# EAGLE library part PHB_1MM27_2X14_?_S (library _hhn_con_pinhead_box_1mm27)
Pin Header Box-Type, 1.27mm/0.5"/50mil Pitch, 2x14 Circuits, single gates in schematic Note: see library description for an important note about THT-version
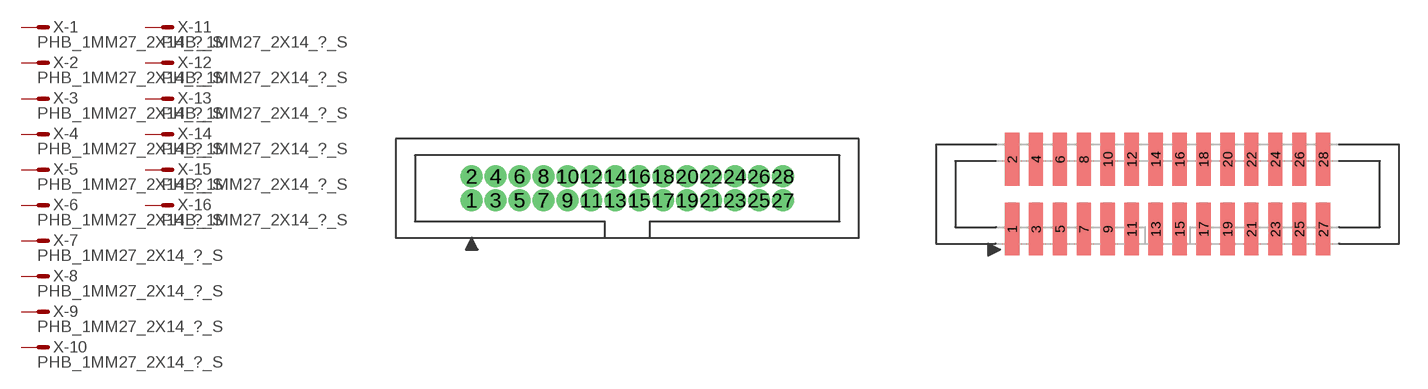
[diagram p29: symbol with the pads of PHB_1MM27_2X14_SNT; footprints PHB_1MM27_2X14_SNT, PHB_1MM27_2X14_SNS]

Designator prefix X; gates -1=M -2=M -3=M -4=M -5=M -6=M -7=M -8=M -9=M -10=M -11=M -12=M -13=M -14=M -15=M -16=M -17=M -18=M -19=M -20=M -21=M -22=M -23=M -24=M -25=M -26=M -27=M -28=M

## PHB_1MM27_2X14_SNT_S  [PHB_1MM27_2X14_SNT]
1  -1:S  pas
2  -2:S  pas
3  -3:S  pas
4  -4:S  pas
5  -5:S  pas
6  -6:S  pas
7  -7:S  pas
8  -8:S  pas
9  -9:S  pas
10  -10:S  pas
11  -11:S  pas
12  -12:S  pas
13  -13:S  pas
14  -14:S  pas
15  -15:S  pas
16  -16:S  pas
17  -17:S  pas
18  -18:S  pas
19  -19:S  pas
20  -20:S  pas
21  -21:S  pas
22  -22:S  pas
23  -23:S  pas
24  -24:S  pas
25  -25:S  pas
26  -26:S  pas
27  -27:S  pas
28  -28:S  pas

## PHB_1MM27_2X14_SNS_S  [PHB_1MM27_2X14_SNS]
Pads as for PHB_1MM27_2X14_SNT

## Footprint PHB_1MM27_2X14_SNT (pad centres in mm)
Pin Header Box-Type, 1.27mm Pitch, 2x14 circuits, Straight, No Locking, THT Important Note: Diameter in this lbr is set to a specific value (NOT 'auto' = 0), this is ignored by actual eagle versions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
drill 0.65 pad 1 round: 1 -8.255,-0.635; 2 -8.255,0.635; 3 -6.985,-0.635; 4 -6.985,0.635; 5 -5.715,-0.635; 6 -5.715,0.635; 7 -4.445,-0.635; 8 -4.445,0.635; 9 -3.175,-0.635; 10 -3.175,0.635; 11 -1.905,-0.635; 12 -1.905,0.635; 13 -0.635,-0.635; 14 -0.635,0.635; 15 0.635,-0.635; 16 0.635,0.635; 17 1.905,-0.635; 18 1.905,0.635; 19 3.175,-0.635; 20 3.175,0.635; 21 4.445,-0.635; 22 4.445,0.635; 23 5.715,-0.635; 24 5.715,0.635; 25 6.985,-0.635; 26 6.985,0.635; 27 8.255,-0.635; 28 8.255,0.635

## Footprint PHB_1MM27_2X14_SNS (pad centres in mm)
Pin Header Box-Type, 1.27mm Pitch, 2x14 circuits, Straight, No Locking, SMT
smd 0.76 x 2.8: 1 -8.255,-1.85; 2 -8.255,1.85; 3 -6.985,-1.85; 4 -6.985,1.85; 5 -5.715,-1.85; 6 -5.715,1.85; 7 -4.445,-1.85; 8 -4.445,1.85; 9 -3.175,-1.85; 10 -3.175,1.85; 11 -1.905,-1.85; 12 -1.905,1.85; 13 -0.635,-1.85; 14 -0.635,1.85; 15 0.635,-1.85; 16 0.635,1.85; 17 1.905,-1.85; 18 1.905,1.85; 19 3.175,-1.85; 20 3.175,1.85; 21 4.445,-1.85; 22 4.445,1.85; 23 5.715,-1.85; 24 5.715,1.85; 25 6.985,-1.85; 26 6.985,1.85; 27 8.255,-1.85; 28 8.255,1.85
